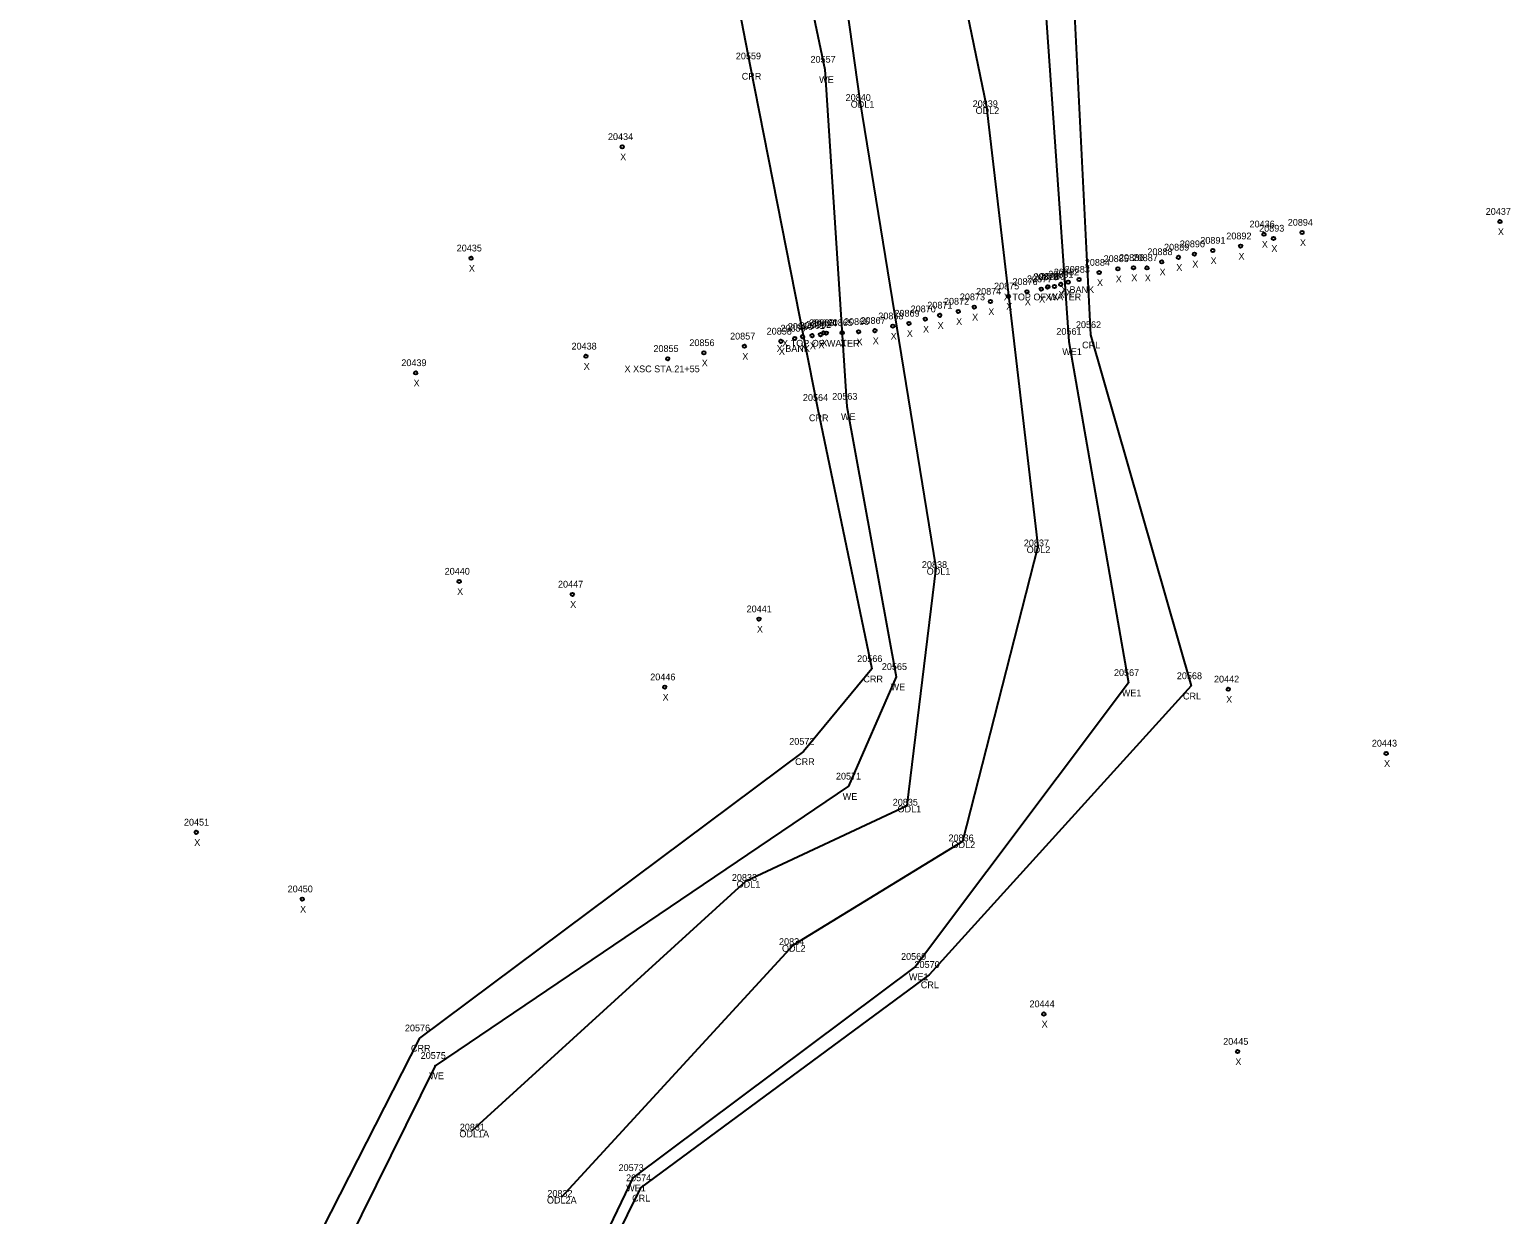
# Model space of a CAD drawing. Extents: x 1966740 to 1969291, y 1117378 to 1118461.
# Drawn here: x 1967789.9 to 1968008.7, y 1118113.2 to 1118288.2 of the extents above; entities that cross this region are included whole.
import ezdxf

# ---------------------------------------------------------------- set-up
doc = ezdxf.new("R2010")
doc.units = 0
for name, color, linetype in [('RD_EX_H2O', 7, 'Continuous'), ('RD_EX_H2O_txCode', 7, 'Continuous'), ('RD_SMD_Locator', 7, 'Continuous'), ('RD_SMD_Misc', 7, 'Continuous')]:
    doc.layers.add(name, color=color, linetype=linetype)

msp = doc.modelspace()

# ---------------------------------------------------------------- linework, layer by layer
at = {"layer": 'RD_EX_H2O'}
for points in [[(1967852.4, 1118390.04), (1967912.21, 1118383.64), (1967925.08, 1118336.82), (1967944.14, 1118294.4), (1967946.67, 1118243.15), (1967961.58, 1118191.28), (1967922.84, 1118148.62), (1967880.18, 1118117.11), (1967858.72, 1118073.64), (1967843.96, 1118030.69), (1967829.77, 1117984.65), (1967829.63, 1117934.73), (1967834.65, 1117903.36)], [(1967852.05, 1118385.41), (1967898.77, 1118376.41), (1967924.08, 1118337.23), (1967939.81, 1118294.93), (1967943.5, 1118242.16), (1967952.29, 1118191.75), (1967920.83, 1118149.81), (1967879.07, 1118118.61), (1967857.7, 1118074.04), (1967841.84, 1118031.93), (1967826.93, 1117984.9), (1967827.73, 1117935.27), (1967832.39, 1117902.59), (1967835.81, 1117893.8), (1967842.37, 1117871.73), (1967853.33, 1117857.05), (1967865.72, 1117824.99), (1967870.38, 1117810.73), (1967864.06, 1117791.33)], [(1967868.55, 1118115.81), (1967902.78, 1118153.01), (1967927.84, 1118168.33), (1967938.95, 1118211.91), (1967931.39, 1118276.79), (1967918, 1118341.48), (1967873.81, 1118373.58)], [(1967855.32, 1118125.6), (1967895.81, 1118162.48), (1967919.58, 1118173.6), (1967923.89, 1118208.71), (1967912.66, 1118277.71), (1967904.34, 1118337.09), (1967865.66, 1118353.94)], [(1967848.72, 1118350.07), (1967881.79, 1118342.06), (1967895.58, 1118338.92), (1967907.43, 1118282.36), (1967910.66, 1118232.56), (1967917.99, 1118192.64), (1967910.91, 1118176.45), (1967849.83, 1118135.18), (1967825.91, 1118086.77), (1967802.99, 1118041.98), (1967795.15, 1117992.28), (1967793.27, 1117935.35), (1967800.64, 1117889.8), (1967800.4, 1117872.52), (1967800.8, 1117854.99), (1967811.67, 1117837.73), (1967837.15, 1117809.04), (1967808.01, 1117752.12)], [(1967848.54, 1118347.45), (1967880.38, 1118337.78), (1967886.93, 1118331.58), (1967896.4, 1118282.85), (1967906.33, 1118232.39), (1967914.38, 1118193.81), (1967904.29, 1118181.59), (1967847.52, 1118139.25), (1967823.99, 1118093.05), (1967800.15, 1118046.69), (1967791.83, 1117992.41), (1967789.93, 1117935.61), (1967798.32, 1117889.19), (1967796.67, 1117880.97)]]:
    msp.add_lwpolyline(points, dxfattribs=at)
at = {"layer": 'RD_SMD_Locator'}
for centre, radius in [((1967896.4, 1118282.85), 0.001), ((1967907.43, 1118282.36), 0.001), ((1967912.66, 1118277.71), 0.001), ((1967931.39, 1118276.79), 0.001), ((1967877.5, 1118270.93), 0.25), ((1968007.19, 1118259.88), 0.25), ((1967972.32, 1118258.02), 0.25), ((1967973.72, 1118257.4), 0.25), ((1967977.94, 1118258.27), 0.25), ((1967962.04, 1118255.09), 0.25), ((1967964.75, 1118255.61), 0.25), ((1967968.87, 1118256.26), 0.25), ((1967855.15, 1118254.47), 0.25), ((1967950.73, 1118252.9), 0.25), ((1967953.04, 1118253.07), 0.25), ((1967955.03, 1118253.04), 0.25), ((1967957.21, 1118253.93), 0.25), ((1967959.67, 1118254.6), 0.25), ((1967942.28, 1118250.61), 0.25), ((1967943.38, 1118250.93), 0.25), ((1967944.99, 1118251.33), 0.25), ((1967947.96, 1118252.35), 0.25), ((1967934.55, 1118248.86), 0.25), ((1967937.29, 1118249.51), 0.25), ((1967939.41, 1118249.92), 0.25), ((1967940.34, 1118250.22), 0.25), ((1967940.4, 1118250.25), 0.25), ((1967941.35, 1118250.29), 0.25), ((1967927.15, 1118246.61), 0.25), ((1967929.5, 1118247.26), 0.25), ((1967931.89, 1118248.08), 0.25), ((1967917.48, 1118244.44), 0.25), ((1967919.85, 1118244.84), 0.25), ((1967922.26, 1118245.48), 0.25), ((1967924.4, 1118246.03), 0.25), ((1967900.95, 1118242.19), 0.25), ((1967902.99, 1118242.63), 0.25), ((1967904.14, 1118242.88), 0.25), ((1967905.54, 1118243.03), 0.25), ((1967906.79, 1118243.18), 0.25), ((1967907.25, 1118243.44), 0.25), ((1967907.65, 1118243.41), 0.25), ((1967909.99, 1118243.46), 0.25), ((1967912.42, 1118243.61), 0.25), ((1967914.83, 1118243.77), 0.25), ((1967943.5, 1118242.16), 0.001), ((1967946.67, 1118243.15), 0.001), ((1967872.12, 1118239.98), 0.25), ((1967884.22, 1118239.62), 0.25), ((1967889.56, 1118240.49), 0.25), ((1967895.54, 1118241.46), 0.25), ((1967846.97, 1118237.53), 0.25), ((1967906.33, 1118232.39), 0.001), ((1967910.66, 1118232.56), 0.001), ((1967938.95, 1118211.91), 0.001), ((1967923.89, 1118208.71), 0.001), ((1967853.4, 1118206.72), 0.25), ((1967870.12, 1118204.81), 0.25), ((1967897.7, 1118201.16), 0.25), ((1967914.38, 1118193.81), 0.001), ((1967917.99, 1118192.64), 0.001), ((1967952.29, 1118191.75), 0.001), ((1967883.77, 1118191.11), 0.25), ((1967961.58, 1118191.28), 0.001), ((1967967.04, 1118190.79), 0.25), ((1967904.29, 1118181.59), 0.001), ((1967990.37, 1118181.32), 0.25), ((1967910.91, 1118176.45), 0.001), ((1967919.58, 1118173.6), 0.001), ((1967814.56, 1118169.65), 0.25), ((1967927.84, 1118168.33), 0.001), ((1967895.81, 1118162.48), 0.001), ((1967830.21, 1118159.79), 0.25), ((1967902.78, 1118153.01), 0.001), ((1967920.83, 1118149.81), 0.001), ((1967922.84, 1118148.62), 0.001), ((1967939.79, 1118142.81), 0.25), ((1967847.52, 1118139.25), 0.001), ((1967968.41, 1118137.26), 0.25), ((1967849.83, 1118135.18), 0.001), ((1967855.32, 1118125.6), 0.001), ((1967879.07, 1118118.61), 0.001), ((1967868.55, 1118115.81), 0.001), ((1967880.18, 1118117.11), 0.001)]:
    msp.add_circle(centre, radius, dxfattribs=at)

# ---------------------------------------------------------------- texts
at = {"layer": 'RD_EX_H2O_txCode'}
for s, p in [('20559', (1967894.28, 1118283.85)), ('20557', (1967905.31, 1118283.36)), ('CRR', (1967895.15, 1118280.85)), ('WE', (1967906.59, 1118280.36)), ('20840', (1967910.5, 1118277.71)), ('ODL1', (1967911.25, 1118276.71)), ('20839', (1967929.27, 1118276.79)), ('ODL2', (1967929.7, 1118275.79)), ('20562', (1967944.53, 1118244.15)), ('20561', (1967941.64, 1118243.16)), ('CRL', (1967945.44, 1118241.15)), ('WE1', (1967942.51, 1118240.16)), ('20564', (1967904.19, 1118233.39)), ('20563', (1967908.52, 1118233.56)), ('CRR', (1967905.08, 1118230.39)), ('WE', (1967909.82, 1118230.56)), ('20837', (1967936.83, 1118211.91)), ('ODL2', (1967937.25, 1118210.91)), ('20838', (1967921.77, 1118208.71)), ('ODL1', (1967922.48, 1118207.71)), ('20566', (1967912.21, 1118194.81)), ('20565', (1967915.85, 1118193.64)), ('CRR', (1967913.12, 1118191.81)), ('20567', (1967950.15, 1118192.75)), ('20568', (1967959.44, 1118192.28)), ('WE', (1967917.15, 1118190.64)), ('WE1', (1967951.31, 1118189.75)), ('CRL', (1967960.35, 1118189.28)), ('20572', (1967902.17, 1118182.59)), ('CRR', (1967903.03, 1118179.59)), ('20571', (1967909.07, 1118177.45)), ('WE', (1967910.07, 1118174.45)), ('20835', (1967917.46, 1118173.6)), ('ODL1', (1967918.17, 1118172.6)), ('20836', (1967925.7, 1118168.33)), ('ODL2', (1967926.15, 1118167.33)), ('20833', (1967893.69, 1118162.48)), ('ODL1', (1967894.4, 1118161.48)), ('20834', (1967900.66, 1118153.01)), ('ODL2', (1967901.09, 1118152.01)), ('20569', (1967918.69, 1118150.81)), ('20570', (1967920.68, 1118149.62)), ('WE1', (1967919.85, 1118147.81)), ('CRL', (1967921.61, 1118146.62)), ('20576', (1967845.38, 1118140.25)), ('CRR', (1967846.27, 1118137.25)), ('20575', (1967847.71, 1118136.18)), ('WE', (1967848.99, 1118133.18)), ('20831', (1967853.49, 1118125.6)), ('ODL1A', (1967853.43, 1118124.6)), ('20573', (1967876.95, 1118119.61)), ('WE1', (1967878.08, 1118116.61)), ('20574', (1967878.06, 1118118.11)), ('ODL2A', (1967866.37, 1118114.81)), ('20832', (1967866.43, 1118115.81)), ('CRL', (1967878.95, 1118115.11))]:
    msp.add_text(s, height=1, dxfattribs=at).set_placement(p)
at = {"layer": 'RD_SMD_Misc'}
for s, p in [('20434', (1967875.38, 1118271.93)), ('X', (1967877.19, 1118268.93)), ('20437', (1968005.08, 1118260.88)), ('20436', (1967970.18, 1118259.02)), ('20894', (1967975.83, 1118259.27)), ('20891', (1967962.91, 1118256.61)), ('20892', (1967966.75, 1118257.26)), ('20893', (1967971.6, 1118258.4)), ('X', (1968006.88, 1118257.88)), ('20435', (1967853.03, 1118255.47)), ('20888', (1967955.09, 1118254.93)), ('20889', (1967957.55, 1118255.6)), ('20890', (1967959.88, 1118256.09)), ('X', (1967968.55, 1118254.26)), ('X', (1967972, 1118256.02)), ('X', (1967973.41, 1118255.4)), ('X', (1967977.63, 1118256.27)), ('X', (1967854.83, 1118252.47)), ('20883', (1967942.87, 1118252.33)), ('20884', (1967945.84, 1118253.35)), ('20885', (1967948.62, 1118253.9)), ('20886', (1967950.9, 1118254.07)), ('20887', (1967952.91, 1118254.04)), ('X', (1967959.36, 1118252.6)), ('X', (1967961.73, 1118253.09)), ('X', (1967964.43, 1118253.61)), ('20875', (1967932.43, 1118249.86)), ('20876', (1967935.15, 1118250.51)), ('20877', (1967937.29, 1118250.92)), ('20879', (1967938.22, 1118251.22)), ('20878', (1967938.28, 1118251.25)), ('20880', (1967939.19, 1118251.29)), ('20881', (1967940.45, 1118251.61)), ('20882', (1967941.27, 1118251.93)), ('X', (1967947.64, 1118250.35)), ('X', (1967950.42, 1118250.9)), ('X', (1967952.72, 1118251.07)), ('X', (1967954.71, 1118251.04)), ('X', (1967956.89, 1118251.93)), ('20872', (1967925.03, 1118247.61)), ('20873', (1967927.38, 1118248.26)), ('20874', (1967929.78, 1118249.08)), ('X TOP OF WATER', (1967933.87, 1118248.25)), ('X', (1967939.09, 1118247.92)), ('X', (1967940.02, 1118248.22)), ('X', (1967941.03, 1118248.29)), ('X', (1967941.97, 1118248.61)), ('X BANK', (1967942.32, 1118249.33)), ('X', (1967943.07, 1118248.93)), ('20868', (1967915.33, 1118245.44)), ('20869', (1967917.71, 1118245.84)), ('20870', (1967920.1, 1118246.48)), ('20871', (1967922.57, 1118247.03)), ('X', (1967931.58, 1118246.08)), ('X', (1967934.23, 1118246.86)), ('X', (1967936.98, 1118247.51)), ('20859', (1967900.88, 1118243.63)), ('20860', (1967901.96, 1118243.88)), ('20861', (1967903.68, 1118244.03)), ('20862', (1967904.65, 1118244.18)), ('20863', (1967905.11, 1118244.44)), ('20864', (1967905.51, 1118244.41)), ('20865', (1967907.85, 1118244.46)), ('20866', (1967910.26, 1118244.61)), ('20867', (1967912.69, 1118244.77)), ('X', (1967921.94, 1118243.48)), ('X', (1967924.09, 1118244.03)), ('X', (1967926.83, 1118244.61)), ('X', (1967929.19, 1118245.26)), ('20856', (1967887.41, 1118241.49)), ('20857', (1967893.43, 1118242.46)), ('20858', (1967898.83, 1118243.19)), ('X TOP OF WATER', (1967901.12, 1118241.41)), ('X', (1967906.48, 1118241.18)), ('X', (1967906.93, 1118241.44)), ('X', (1967909.68, 1118241.46)), ('X', (1967912.11, 1118241.61)), ('X', (1967914.51, 1118241.77)), ('X', (1967917.16, 1118242.44)), ('X', (1967919.54, 1118242.84)), ('20438', (1967870, 1118240.98)), ('20855', (1967882.1, 1118240.62)), ('X', (1967895.23, 1118239.46)), ('X BANK', (1967900.32, 1118240.63)), ('X', (1967900.64, 1118240.19)), ('X', (1967903.83, 1118240.88)), ('X', (1967905.22, 1118241.03)), ('20439', (1967844.85, 1118238.53)), ('X', (1967871.8, 1118237.98)), ('X XSC STA.21+55', (1967877.83, 1118237.62)), ('X', (1967889.24, 1118238.49)), ('X', (1967846.66, 1118235.53)), ('20440', (1967851.25, 1118207.72)), ('X', (1967853.09, 1118204.72)), ('20447', (1967868, 1118205.81)), ('X', (1967869.8, 1118202.81)), ('20441', (1967895.87, 1118202.16)), ('X', (1967897.39, 1118199.16)), ('20446', (1967881.63, 1118192.11)), ('20442', (1967964.93, 1118191.79)), ('X', (1967883.46, 1118189.11)), ('X', (1967966.73, 1118188.79)), ('20443', (1967988.26, 1118182.32)), ('X', (1967990.06, 1118179.32)), ('20451', (1967812.73, 1118170.65)), ('X', (1967814.25, 1118167.65)), ('20450', (1967828.05, 1118160.79)), ('X', (1967829.89, 1118157.79)), ('20444', (1967937.67, 1118143.81)), ('X', (1967939.47, 1118140.81)), ('20445', (1967966.29, 1118138.26)), ('X', (1967968.09, 1118135.26))]:
    msp.add_text(s, height=1, dxfattribs=at).set_placement(p)

doc.saveas('drawing.dxf')
